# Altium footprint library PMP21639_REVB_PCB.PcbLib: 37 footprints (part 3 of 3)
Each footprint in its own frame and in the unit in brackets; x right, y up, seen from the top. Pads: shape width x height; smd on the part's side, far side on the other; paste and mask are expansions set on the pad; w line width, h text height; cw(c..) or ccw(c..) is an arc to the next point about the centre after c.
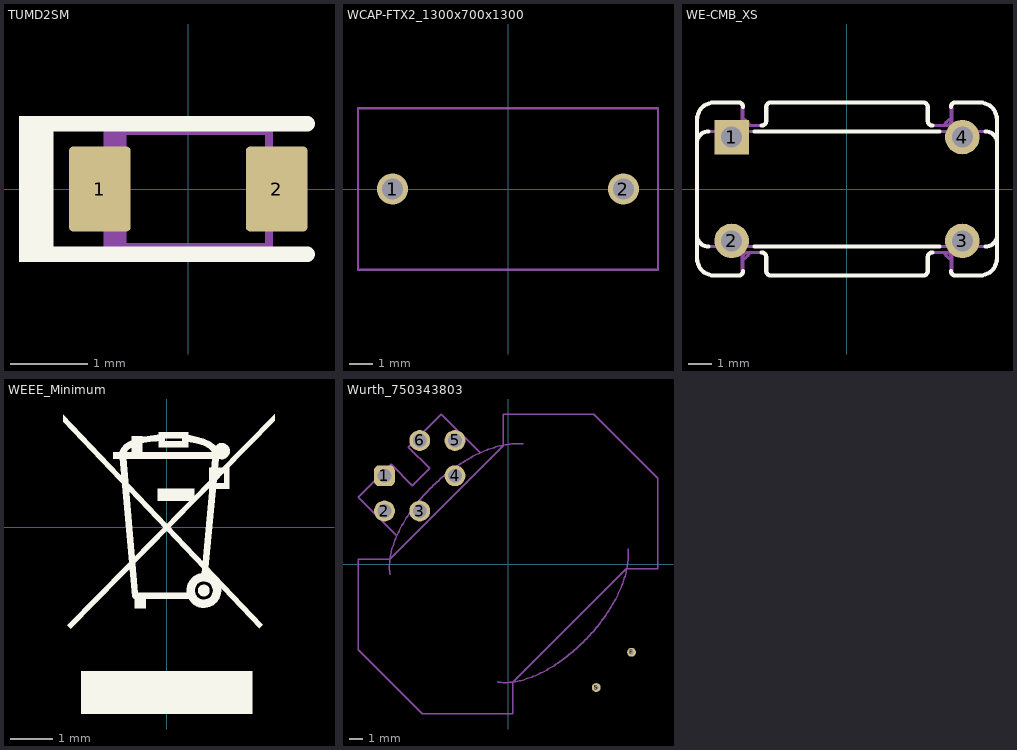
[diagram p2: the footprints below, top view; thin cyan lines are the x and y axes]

## TUMD2SM [mm] "SMD, 2-Leads, Body 2x1.4mm"
height 0.8
pads (2):
  rrect12% 0.8x1.1 smd: 1(-1.15,0) 2(1.15,0)
Top Overlay:
  rectangle: -2.2,-0.95 -1.8,0.95
  lines w0.2: 1.55,-0.85 -1.85,-0.85 -1.85,0.85 1.55,0.85
Mechanical 5:
  rectangle: -1.05,-0.75 -0.8,0.75
  lines w0.1: -1.05,-0.425 -1.35,-0.425 -1.35,0.425 -1.05,0.425 ; 1.05,-0.425 1.35,-0.425 1.35,0.425 1.05,0.425 ; -1.05,-0.75 -1.05,0.75 1.05,0.75 1.05,-0.75 -1.05,-0.75
  text ".Designator" at -0.7,-0.2 h0.4
3D body: height 0.8, standoff 0.8, extent -1.05,-0.75 -0.8,0.75
3D body: height 0.27, standoff 0, extent 1.05,-0.425 1.35,0.425
3D body: height 0.27, standoff 0, extent -1.35,-0.425 -1.05,0.425
3D body: height 0.8, standoff 0, extent -1.05,-0.75 1.05,0.75

## WCAP-FTX2_1300x700x1300 [mm] "TH, 2-Leads, Body 13x7mm, Pin Spacing 10mm"
height 13.5
pads (2):
  round 1.35 hole 0.9: 1(-5,0) 2(5,0)
Mechanical 5:
  lines w0.1: -6.5,-3.5 6.5,-3.5 6.5,3.5 -6.5,3.5 -6.5,-3.5
  text ".Designator" at -1.8,-0.514 h1.02
3D body "890324023023.stp": height 13, standoff -20, extent -6.5,-3.5 6.5,3.5

## WE-CMB_XS [mm] "WE-CMB Series Size XS"
height 18
pads (4):
  rect 1.5x1.5 hole 0.9: 1(-5,2.25)
  round 1.5 hole 0.9: 2(-5,-2.25) 3(5,-2.25) 4(5,2.25)
Top Overlay:
  lines w0.178: -6,-2.5 cw(c-6,-2) -6.5,-2 ; -6,2.5 ccw(c-6,2) -6.5,2 ; -4.5,-3.55 cw(c-4.7,-3.55) -4.543,-3.674 cw(c-4.7,-3.55) -4.7,-3.75 -5.75,-3.75 cw(c-5.75,-3) -6.5,-3 -6.5,-2 ; -4.5,3.55 ccw(c-4.7,3.55) -4.543,3.674 ccw(c-4.7,3.55) -4.7,3.75 -5.75,3.75 ccw(c-5.75,3) -6.5,3 -6.5,2 ; -4,-2.5 0,-2.5 4,-2.5 ; -4,2.5 0,2.5 4,2.5 ; -3.7,-2.75 cw(c-3.7,-2.95) -3.5,-2.95 -3.5,-3.55 ccw(c-3.3,-3.55) -3.3,-3.75 3.3,-3.75 ccw(c3.3,-3.55) 3.5,-3.55 3.5,-2.95 cw(c3.7,-2.95) 3.7,-2.75 ; -3.7,2.75 ccw(c-3.7,2.95) -3.5,2.95 -3.5,3.55 cw(c-3.3,3.55) -3.3,3.75 3.3,3.75 cw(c3.3,3.55) 3.5,3.55 3.5,2.95 ccw(c3.7,2.95) 3.7,2.75 ; 4.5,-3.55 ccw(c4.7,-3.55) 4.543,-3.674 ccw(c4.7,-3.55) 4.7,-3.75 5.75,-3.75 ccw(c5.75,-3) 6.5,-3 6.5,-2 ; 4.5,3.55 cw(c4.7,3.55) 4.543,3.674 cw(c4.7,3.55) 4.7,3.75 5.75,3.75 cw(c5.75,3) 6.5,3 6.5,2 ; 6,-2.5 ccw(c6,-2) 6.5,-2 ; 6,2.5 cw(c6,2) 6.5,2 ; -6.5,-2 -6.5,2 ; 6.5,-2 6.5,2
Mechanical 5:
  lines w0.127: -4.543,-2.5 -4.543,-3.674 ; -4.543,2.5 -4.543,3.674 ; -4.5,-3.058 ccw(c-5,-2.25) -4.192,-2.75 ; -4.5,3.058 cw(c-5,2.25) -4.192,2.75 ; 4.192,-2.75 ccw(c5,-2.25) 4.5,-3.058 ; 4.192,2.75 cw(c5,2.25) 4.5,3.058 ; 4.543,-2.5 4.543,-3.674 ; 4.543,2.5 4.543,3.674 ; -6.5,-2 ccw(c-6,-2) -6,-2.5 0,-2.5 6,-2.5 ccw(c6,-2) 6.5,-2 ; -6.5,-2 -6.5,-3 ccw(c-5.75,-3) -5.75,-3.75 -4.7,-3.75 ccw(c-4.7,-3.55) -4.543,-3.674 ; -6.5,-2 -6.5,2 ; -6.5,2 cw(c-6,2) -6,2.5 0,2.5 6,2.5 cw(c6,2) 6.5,2 ; -6.5,2 -6.5,3 cw(c-5.75,3) -5.75,3.75 -4.7,3.75 cw(c-4.7,3.55) -4.543,3.674 ; -4.543,-3.674 ccw(c-4.7,-3.55) -4.5,-3.55 -4.5,-2.95 cw(c-4.3,-2.95) -4.3,-2.75 -3.7,-2.75 cw(c-3.7,-2.95) -3.5,-2.95 -3.5,-3.55 ccw(c-3.3,-3.55) -3.3,-3.75 3.3,-3.75 ccw(c3.3,-3.55) 3.5,-3.55 3.5,-2.95 cw(c3.7,-2.95) 3.7,-2.75 4.3,-2.75 cw(c4.3,-2.95) 4.5,-2.95 4.5,-3.55 ccw(c4.7,-3.55) 4.543,-3.674 ; -4.543,3.674 cw(c-4.7,3.55) -4.5,3.55 -4.5,2.95 ccw(c-4.3,2.95) -4.3,2.75 -3.7,2.75 ccw(c-3.7,2.95) -3.5,2.95 -3.5,3.55 cw(c-3.3,3.55) -3.3,3.75 3.3,3.75 cw(c3.3,3.55) 3.5,3.55 3.5,2.95 ccw(c3.7,2.95) 3.7,2.75 4.3,2.75 ccw(c4.3,2.95) 4.5,2.95 4.5,3.55 cw(c4.7,3.55) 4.543,3.674 ; 4.543,-3.674 ccw(c4.7,-3.55) 4.7,-3.75 5.75,-3.75 ccw(c5.75,-3) 6.5,-3 6.5,-2 ; 4.543,3.674 cw(c4.7,3.55) 4.7,3.75 5.75,3.75 cw(c5.75,3) 6.5,3 6.5,2 ; 6.5,-2 6.5,2
  text ".Designator" at -2.65,-0.375 h1.02
3D body "WE-CMB_XS.stp": height 16.24, standoff -3.58, extent -6.5,-3.75 6.5,3.75

## WEEE_Minimum [mm] "WEEElie bin"
Top Overlay:
  drawing of 23 lines, arcs and shapes, not listed

## Wurth_750343803 [mm] "TH, 8-Leads, Body 21.59x21.59mm"
height 17.27
pads (8):
  rrect50% 1.5x1.5 hole 1: 1(-8.89,6.35)
  round 1.5 hole 1: 2(-8.89,3.81) 3(-6.35,3.81) 4(-3.81,6.35) 5(-3.81,8.89) 6(-6.35,8.89)
  round 0.635 hole 0.305: F(8.89,-6.35) S(6.35,-8.89)
Mechanical 5:
  drawing of 222 lines, arcs and shapes, not listed
  text ".Designator" at -1.8,-0.514 h1.02
3D body "750343803.stp": height 17.27, standoff -2.03, extent -10.795,-10.795 10.795,10.795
